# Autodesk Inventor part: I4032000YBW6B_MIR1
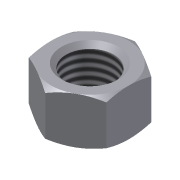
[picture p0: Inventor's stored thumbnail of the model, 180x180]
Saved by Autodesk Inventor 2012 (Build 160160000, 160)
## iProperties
Company: CAD-Verlag
Shininess: 64.0
Length Units: 11269
Angle Units: 11279
Time Units: 11290
Mass Units: 11283
Length Display Precision: 3
Angle Display Precision: 2
Compacted: True
Part Number: I4032000YBW6B_MIR1
Document SubType Name: Modeling
Created: 2004-09
Material: Steel, Mild
Designer: Greiling
Manufacturer: Standard
Standards Organization: Custom
Density: 1 g/cm^3
Density: 0.0
Volumn: 0.0
Area: 0.0
PropertySet Name: Model Information
Control State: 0
Master: False
Checked Out: False
Author: Jürgen Kronas
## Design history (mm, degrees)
node "Mutter DIN EN 24 032 M12" dims "d0" = 10, "d64" = 0
  node "WorkPlane8"
  node "WorkPlane10"
  node "MSC_PT1"
  node "MSC_PT2"
  node "MSC_PF1"
  node "MSC_A1"
  node "WorkPoint1"
  node "WorkPoint2"
node "Volumenkörper1"
node "Volumenkörpern"
node "Oberflächenkörpern"
tag "Bezeichnung2"
feature "Volumenkörper1::Mutter DIN EN 24 032 M12" dims "d0" = 10, "d64" = 0
